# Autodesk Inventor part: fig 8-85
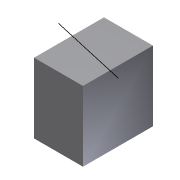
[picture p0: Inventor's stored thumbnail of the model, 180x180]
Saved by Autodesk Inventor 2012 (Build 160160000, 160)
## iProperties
Created: 2009-04
Part Number: fig 8-85
Document SubType Name: Modeling
Designer: Sham
Density: 1 g/cm^3
Material: Default
Author: Sham
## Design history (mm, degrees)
sketch "Sketch5"
  geometry: L1 (14, -20)-(0, -20); L2 (0, -20)-(0, 0); L3 (0, 0)-(14, 0); L4 (14, 0)-(14, -20)
  constraints: 8 end point
extrude "Extrusion2" new body sketch "Sketch5" distance "d3" = 20; taper "d4" = 0 deg
sketch "Sketch6"
  geometry: L1 (-5, 12)-(17, 7)
  constraints: 2 end point
body "Solid2"
